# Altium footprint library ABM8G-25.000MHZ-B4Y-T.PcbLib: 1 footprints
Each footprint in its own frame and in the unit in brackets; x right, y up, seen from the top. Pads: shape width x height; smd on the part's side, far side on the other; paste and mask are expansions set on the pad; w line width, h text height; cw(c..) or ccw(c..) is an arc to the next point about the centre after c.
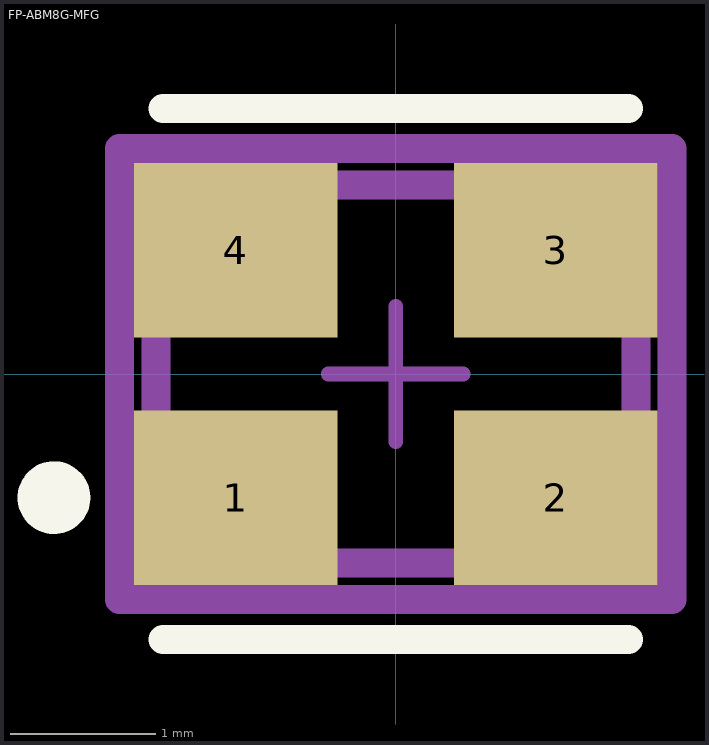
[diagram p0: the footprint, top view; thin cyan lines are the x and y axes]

## FP-ABM8G-MFG [mm]
pads (4):
  rect 1.4x1.2 smd paste+0 mask+0: 1(-1.1,-0.85) 2(1.1,-0.85) 3(1.1,0.85) 4(-1.1,0.85)
Top Overlay:
  circle w0.25: c-2.35,-0.85 r0.125
  lines w0.2: -1.6,-1.825 1.6,-1.825 ; -1.6,1.825 1.6,1.825
Top Assembly:
  lines w0.2: -1.9,-1.55 -1.9,1.55 1.9,1.55 1.9,-1.55 -1.9,-1.55
  text ".Designator" at 0,0.188 h1
Top 3D Body:
  lines w0.2: -1.65,-1.3 -1.65,1.3 1.65,1.3 1.65,-1.3 -1.65,-1.3
Top Courtyard:
  lines w0.2: -1.9,-1.55 -1.9,1.55 1.9,1.55 1.9,-1.55 -1.9,-1.55
Top Component Center:
  lines w0.1: -0.465,0 0.465,0 ; 0,-0.465 0,0.465
3D body "Crys_Abracon_ABM8G-12_288MHZ-18-D2Y-T3_eec.STEP": height 0.25, standoff 0, extent -1.9,-1.55 1.9,1.55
